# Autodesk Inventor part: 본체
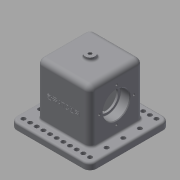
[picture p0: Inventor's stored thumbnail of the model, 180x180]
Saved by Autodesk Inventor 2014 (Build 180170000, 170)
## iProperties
Created: 2018-11
Part Number: 본체
Material: 일반
Document SubType Name: Modeling
Designer: kh
Density: 1 g/cm^3
Appearance: 기본값
Mass: 376.664 g
Surface Area: 777.107 cm^2
Volume: 376.664 cm^3
Author: kh
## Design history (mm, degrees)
sketch "스케치1"
  geometry: L1 (-50, -60)-(50, -60); L2 (60, -50)-(60, 50); L3 (50, 60)-(-50, 60); L4 (-60, 50)-(-60, -50); L5 (-60, -60)-(60, 60); L6 (60, -60)-(-60, 60); A1 r 10 centre (-50, 50) between (-50, 60) and (-60, 50); A2 r 10 centre (50, 50) between (60, 50) and (50, 60); A3 r 10 centre (50, -50) between (50, -60) and (60, -50); A4 r 10 centre (-50, -50) between (-60, -50) and (-50, -60); 2 further points
  constraints: 12 end point, 8 point on circle, 8 point on line, 8 tangent, 4 centre point, 3 equal radius, 2 midpoint, 2 parallel, 1 coincident, 1 horizontal, 1 perpendicular
  dimensions: "d0" = 120 distance of L5.end L6.end; "d1" = 120 distance of L6.start L5.end; "d2" = 10 radius of A1
extrude "돌출1" new body sketch "스케치1" distance "d3" = 10; taper "d4" = 0 deg
hole "구멍1" sketch "스케치1" diameter "d5" = 6.6; stored, may be unused: countersink angle "d9" = 90 deg, drill point angle "d11" = 118 deg; dims "d6" = 6, "d7" = 4, "d8" = 2, "d10" = 8
sketch "스케치2"
  geometry: L1 (-40, -40)-(40, -40); L2 (40, -40)-(40, 40); L3 (40, 40)-(-40, 40); L4 (-40, 40)-(-40, -40); L5 (-40, -40)-(40, 40); L6 (40, -40)-(-40, 40); 1 further point
  constraints: 12 end point, 2 midpoint, 2 parallel, 1 horizontal, 1 perpendicular
  dimensions: "d18" = 80 distance of L3.end L2.end; "d19" = 80 distance of L1.end L2.end
extrude "돌출2" join sketch "스케치2" distance "d20" = 80; taper "d21" = 0 deg
sketch "스케치3"
  geometry: L1 (-23, -30)-(23, -30); L2 (23, -30)-(23, 30); L3 (23, 30)-(-23, 30); L4 (-23, 30)-(-23, -30); L5 (-23, -30)-(23, 30); L6 (23, -30)-(-23, 30); 1 further point
  constraints: 12 end point, 2 midpoint, 2 parallel, 1 horizontal, 1 perpendicular
  dimensions: "d22" = 46 distance of L3.end L2.end; "d23" = 60 distance of L1.end L2.end
extrude "돌출3" cut sketch "스케치3" distance "d24" = 80; taper "d25" = 0 deg
node "작업 평면1"
sketch "스케치4"
  geometry: C1 r 7.5 at (0, 0); 1 further point
  constraints: 1 centre point, 1 coincident
  dimensions: "d27" = 15 diameter of C1
extrude "돌출4" join sketch "스케치4" stored distance "d28" = 60; taper "d29" = 0 deg
hole "구멍2" diameter "d32" = 4.917; stored, may be unused: countersink angle "d36" = 90 deg, drill point angle "d38" = 118 deg; dims "d33" = 15, "d34" = 4, "d35" = 2, "d37" = 8, "d39" = 10, "d40" = 10
sketch "스케치5"
  geometry: L1 (23, 0)-(-23, 0) reference; L2 (23, 0)-(23, 80) reference; L3 (23, 80)-(-23, 80) reference; L4 (-23, 0)-(-23, 80) reference; L5 (-40, 10)-(40, 10) reference; L6 (-40, 10)-(-40, 90) reference; L7 (40, 90)-(-40, 90) reference; L8 (40, 10)-(40, 90) reference; L9 (50, 0)-(-50, 0) reference; L10 (-50, 0)-(-50, 10) reference; L11 (50, 10)-(-50, 10) reference; L12 (50, 0)-(50, 10) reference; L13 (40, 48)-(-40, 48); L14 (-40, 48)-(-40, 68); L15 (-26, 68)-(-40, 68); L16 (-26, 68)-(-26, 64.5); L17 (-26, 64.5)-(-23, 64.5); L18 (40, 48)-(40, 68); L19 (40, 68)-(26, 68); L20 (26, 68)-(26, 64.5); L21 (26, 64.5)-(23, 64.5); L22 (23, 64.5)-(23, 48); L23 (-23, 64.5)-(-23, 48); 1 further point
  constraints: 22 end point, 10 point on line, 6 perpendicular, 1 parallel
  dimensions: "d41" = 48 distance between parallel lines of L1 L13; "d42" = 3 distance of L20.end L21.end; "d43" = 3 distance of L16.end L17.end; "d44" = 40 diameter of L15 L13; "d45" = 33 diameter of L17 L13; "d46" = 33 diameter of L21 L13; "d47" = 40 diameter of L19 L13
revolve "회전1" sketch "스케치5" stored, may be unused: angle "d48" = 90 deg
sketch "스케치6"
  geometry: L1 (0, 80)-(0, 0) reference; L2 (0, 80)-(-80, 80) reference; L3 (-80, 0)-(-80, 80) reference; L4 (0, 0)-(-80, 0) reference; L5 (-64, 40)-(-12, 40); L6 (-38, 66)-(-38, 14); C1 r 20 at (-38, 40) reference; A1 r 26 centre (-38, 40) between (-64, 40) and (-12, 40); 5 further points
  constraints: 5 coincident, 4 end point, 4 point on circle, 1 centre point, 1 parallel, 1 perpendicular
  dimensions: "d49" = 52 diameter of A1; "d50" = 52 distance of L5.start L5.end; "d51" = 52 distance of L6.start L6.end
hole "구멍3" sketch "스케치6" at (-64, 40), (-38, 66), (-12, 40), (-38, 14) diameter "d52" = 3.242; stored, may be unused: countersink angle "d56" = 90 deg, drill point angle "d58" = 118 deg; dims "d53" = 8, "d54" = 4, "d55" = 2, "d57" = 10
chamfer "모따기1" distance "d59" = 1; stored, may be unused: second distance "d60" = 2, angle "d61" = 45 deg
fillet "모깎기1" dims "d62" = 3, "d63" = 0.6, "d64" = 8
sketch "스케치7"
  geometry: L1 (-18, -13)-(82, -13) reference; L2 (72, 0)-(72, 69) reference; L3 (6.698, 38.662)-(57.302, 38.662); L4 (57.302, 38.662)-(57.302, 31.338); L5 (57.302, 31.338)-(6.698, 31.338); L6 (6.698, 31.338)-(6.698, 38.662); L7 (6.698, 35)-(57.302, 35); L8 (32, 38.662)-(32, 31.338); 1 further point
  constraints: 4 end point, 4 midpoint, 2 other
  dimensions: "d65" = 40 distance between parallel lines of L2 L8; "d66" = 48 distance between parallel lines of L1 L7
feature "엠보싱1" sketch "스케치7" dims "d67" = 0.5, "d68" = 0
node "솔리드1"
pattern_linear "직사각형 패턴1" dims "d14" = 10
mirror "대칭1"
pattern_linear "직사각형 패턴2" dims "d17" = 25
mirror "대칭2"
mirror "대칭3"
node "투영된 루프1"
node "투영된 루프2"
node "투영된 루프3"
node "투영된 루프4"
other parameters: "d26" = 5
